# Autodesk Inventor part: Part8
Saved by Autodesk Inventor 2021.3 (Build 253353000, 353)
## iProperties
Created: 2023-01
Part Number: Part8
Material: Generic
Document SubType Name: Modeling
Designer: AdminForWorker
Density: 1 g/cm^3
Appearance: Default
Author: AdminForWorker
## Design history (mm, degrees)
feature "SingleBearingStandoff"
body "Solid1"
